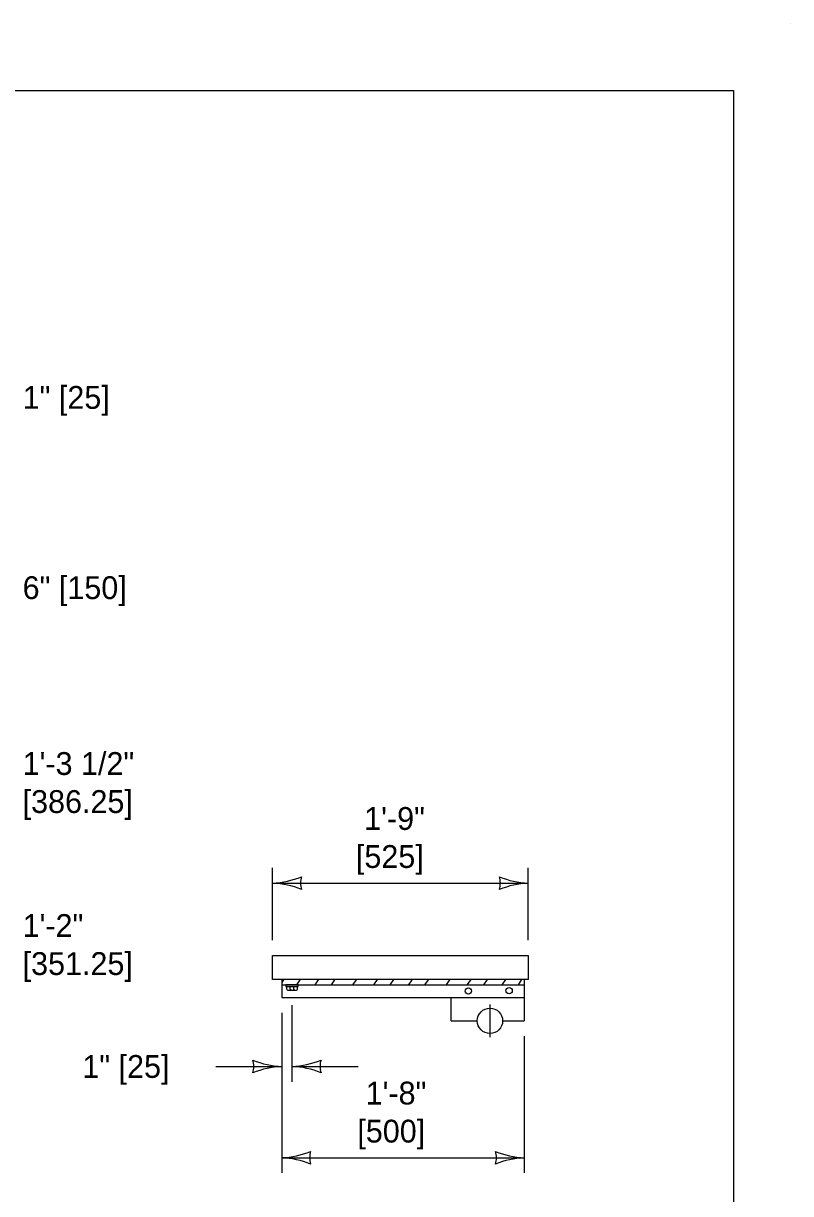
# Model space of a CAD drawing. Extents: x 49991.4 to 50021, y 49987.6 to 50011.4.
# Drawn here: x 50014.882 to 50016.9, y 49996.099 to 49999.176 of the extents above; entities that cross this region are included whole.
import ezdxf

# ---------------------------------------------------------------- set-up
doc = ezdxf.new("R2010")
doc.units = 0
for name, color, linetype in [('Level 1', 7, 'Continuous'), ('Level 2', 7, 'Continuous'), ('Level 3', 7, 'Continuous'), ('Level 5', 7, 'Continuous')]:
    doc.layers.add(name, color=color, linetype=linetype)

msp = doc.modelspace()

# ---------------------------------------------------------------- linework, layer by layer
at = {"layer": 'Level 1'}
for p, q in [((50016.9001, 49999.1756), (50016.9001, 49999.1756)), ((50015.5617, 49996.6609), (50015.5617, 49996.6144)), ((50015.5626, 49996.6541), (50015.5674, 49996.6613)), ((50015.6016, 49996.648), (50015.6103, 49996.6611)), ((50015.6493, 49996.6476), (50015.6582, 49996.6608)), ((50015.6922, 49996.6474), (50015.7011, 49996.6606)), ((50015.749, 49996.6474), (50015.758, 49996.6606)), ((50015.8042, 49996.6478), (50015.8136, 49996.6617)), ((50015.8472, 49996.6476), (50015.8566, 49996.6615)), ((50015.8949, 49996.6472), (50015.9044, 49996.6613)), ((50015.9385, 49996.6479), (50015.9474, 49996.6611)), ((50015.9953, 49996.6479), (50016.0042, 49996.6611)), ((50016.0505, 49996.6482), (50016.0599, 49996.6622)), ((50016.0934, 49996.648), (50016.1028, 49996.662)), ((50016.1412, 49996.6477), (50016.1507, 49996.6617)), ((50016.1841, 49996.6475), (50016.1936, 49996.6615)), ((50016.1997, 49996.6617), (50016.1997, 49996.5531)), ((50015.5617, 49996.6477), (50016.0744, 49996.6477)), ((50015.5751, 49996.6367), (50015.5751, 49996.643)), ((50015.5777, 49996.6341), (50015.6003, 49996.6341)), ((50015.5843, 49996.6366), (50015.5843, 49996.643)), ((50015.5935, 49996.6366), (50015.5935, 49996.643)), ((50015.6028, 49996.6367), (50015.6028, 49996.643)), ((50016.0744, 49996.6477), (50016.1997, 49996.6477)), ((50016.1412, 49996.6477), (50016.1997, 49996.6477)), ((50015.5617, 49996.6144), (50016.0071, 49996.6144)), ((50016.0071, 49996.5531), (50016.0071, 49996.6144)), ((50016.0071, 49996.6144), (50016.0118, 49996.6144)), ((50016.0118, 49996.6144), (50016.1412, 49996.6144)), ((50016.1412, 49996.6144), (50016.1997, 49996.6144)), ((50016.0071, 49996.5531), (50016.0761, 49996.5531)), ((50016.1426, 49996.5531), (50016.1997, 49996.5531))]:
    msp.add_line(p, q, dxfattribs=at)
for points in [[(49999.3835, 49998.9992), (50016.7501, 49998.9992), (50016.7501, 49987.7988), (49999.3835, 49987.7988)], [(50016.2101, 49996.7251), (50016.2101, 49996.6617), (50015.5377, 49996.6617), (50015.5377, 49996.7251)], [(50015.5724, 49996.6477), (50015.5724, 49996.643), (50015.6052, 49996.643), (50015.6052, 49996.6477)]]:
    msp.add_lwpolyline(points, close=True, dxfattribs=at)
for centre, radius in [((50016.0524, 49996.6315), 0.00843), ((50016.1597, 49996.6323), 0.00843), ((50016.1094, 49996.5531), 0.0333)]:
    msp.add_circle(centre, radius, dxfattribs=at)
for centre, start, end in [((50015.5777, 49996.6366), 180, 270), ((50015.5818, 49996.6366), 270, 0), ((50015.5869, 49996.6366), 180, 270), ((50015.591, 49996.6366), 270, 0), ((50015.5961, 49996.6366), 180, 270), ((50015.6002, 49996.6366), 270, 0)]:
    msp.add_arc(centre, 0.00257, start, end, dxfattribs=at)
at = {"layer": 'Level 3'}
for p, q in [((50015.5377, 49996.7651), (50015.5377, 49996.9551)), ((50016.2101, 49996.7651), (50016.2101, 49996.9551)), ((50015.5377, 49996.9151), (50016.2101, 49996.9151)), ((50015.589, 49996.3931), (50015.589, 49996.594)), ((50015.5617, 49996.5744), (50015.5617, 49996.1531)), ((50016.1997, 49996.5131), (50016.1997, 49996.1531)), ((50015.3883, 49996.4331), (50015.5617, 49996.4331)), ((50015.589, 49996.4331), (50015.7624, 49996.4331)), ((50015.5617, 49996.1931), (50016.1997, 49996.1931))]:
    msp.add_line(p, q, dxfattribs=at)
for centre, radius, start, end in [((50015.5262, 49997.1478), 0.233, 272.8273, 292.0772), ((50015.6659, 49996.9151), 0.0548, 162.1388, 197.8612), ((50016.2193, 49997.1372), 0.2223, 247.456, 267.6395), ((50016.0819, 49996.9151), 0.0548, 342.1388, 17.8612), ((50015.5285, 49996.693), 0.2223, 67.456, 87.6395), ((50016.2216, 49996.6824), 0.233, 92.8273, 112.0772), ((50015.5709, 49996.6552), 0.2223, 247.456, 267.6395), ((50015.4335, 49996.4331), 0.0548, 342.1388, 17.8612), ((50015.5775, 49996.6658), 0.233, 272.8273, 292.0772), ((50015.7172, 49996.4331), 0.0548, 162.1388, 197.8612), ((50015.5732, 49996.2004), 0.233, 92.8273, 112.0772), ((50015.5798, 49996.211), 0.2223, 67.456, 87.6395), ((50015.5502, 49996.4258), 0.233, 272.8273, 292.0772), ((50015.5525, 49995.971), 0.2223, 67.456, 87.6395), ((50015.6899, 49996.1931), 0.0548, 162.1388, 197.8612), ((50016.2089, 49996.4152), 0.2223, 247.456, 267.6395), ((50016.0715, 49996.1931), 0.0548, 342.1388, 17.8612), ((50016.2112, 49995.9604), 0.233, 92.8273, 112.0772)]:
    msp.add_arc(centre, radius, start, end, dxfattribs=at)
at = {"layer": 'Level 5'}
msp.add_line((50016.1093, 49996.5964), (50016.1093, 49996.5099), dxfattribs=at)

# ---------------------------------------------------------------- texts
at = {"layer": 'Level 2'}
for s, p in [('1" [25]', (50014.8802, 49998.1622)), ('6" [150]', (50014.8802, 49997.662)), ('1\'-3 1/2"', (50014.8802, 49997.1996)), ('[386.25]', (50014.8802, 49997.0996)), ('1\'-9"', (50015.7785, 49997.0551)), ('[525]', (50015.7568, 49996.9551)), ('1\'-2"', (50014.8802, 49996.7736)), ('[351.25]', (50014.8802, 49996.6736)), ('1" [25]', (50015.0372, 49996.4031)), ('1\'-8"', (50015.7824, 49996.3331)), ('[500]', (50015.7606, 49996.2331))]:
    msp.add_text(s, height=0.06, dxfattribs=at).set_placement(p)

doc.saveas('drawing.dxf')
